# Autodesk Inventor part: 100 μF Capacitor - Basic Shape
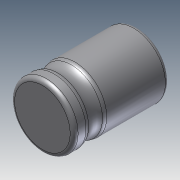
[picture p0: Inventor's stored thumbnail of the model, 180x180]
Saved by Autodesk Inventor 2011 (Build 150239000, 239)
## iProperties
Created: 2013-03
Part Number: 100 μF Capacitor - Basic Shape
Document SubType Name: Modeling
Designer: Lance
Density: 1 g/cm^3
Author: Lance
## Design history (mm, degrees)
sketch "Sketch1"
  geometry: L1 (0, 6)-(3.5, 6); L2 (3.5, -6)-(0, -6); L3 (0, -6)-(0, 6); L4 (4, 5.5)-(4, -1.892); L5 (4, -4.508)-(4, -5.5); A1 r 1 centre (3, -1.892) between (3.9, -2.328) and (4, -1.892); A2 r 2 centre (5.7, -3.2) between (3.9, -2.328) and (3.9, -4.072); A3 r 1 centre (3, -4.508) between (4, -4.508) and (3.9, -4.072); A4 r 0.5 centre (3.5, 5.5) between (4, 5.5) and (3.5, 6); A5 r 0.5 centre (3.5, -5.5) between (3.5, -6) and (4, -5.5); 2 further points
  constraints: 10 end point, 10 point on circle, 10 tangent, 5 centre point, 3 parallel, 2 equal radius, 2 perpendicular, 1 coincident, 1 horizontal, 1 midpoint
  dimensions: "d0" = 1 radius of A1; "d1" = 2 radius of A2; "d2" = 0.3 distance edge to line of A2 L4; "d3" = 2.8 distance from line of A2.centre L2; "d4" = 12 distance between parallel lines of L2 L1; "d5" = 8 diameter of L4 L3; "d6" = 0.5 radius of A4
revolve "Revolution1" sketch "Sketch1" stored, may be unused: angle "d7" = 90 deg
body "Solid1"
